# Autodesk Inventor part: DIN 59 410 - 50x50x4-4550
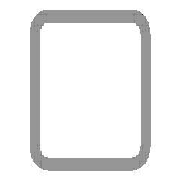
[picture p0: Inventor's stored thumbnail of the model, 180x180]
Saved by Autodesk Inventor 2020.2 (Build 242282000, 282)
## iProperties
Manager: www.cadconsulting.pl
Company: Fabian Stasiak CAD Consulting
IsCustomPart: 1
_CCFamilyMember: 40
_CCFamilyDisplayName: DIN 59410 (Kwadrat) - Rurki stalowe o przekroju kwadratowym formowane na gorąco
_FrameMemberDoc: Frame Member File
_Version: 15.0.0
_GetPNFromCC: 1
Created: 2015-01
Part Number: DIN 59 410 - 50x50x4-4550
Material: Stal, miękka
Description: Rurki stalowe o przekroju kwadratowym formowane na gorąco
Document SubType Name: Modellieren
Standard: DIN
Designer: F.Stasiak
Standards Organization: DIN
Language: pl-PL
Size Designation: 50x50x4
Categories: <MemberInstance><Categories><Category DisplayName="Kształtowniki konstrukcyjne" InternalName="089c4875-fa83-4c05-b084-43b9cc11f5ed" Mnemonic="GRDR"><CategoryPar
Stock Number: 50x50x4
Density: 7.85 g/cm^3
Appearance: Częściowo polerowana
Mass: 24543.7 g
Surface Area: 15652.6 cm^2
Volume: 3126.58 cm^3
Catalog Web Link: www.expertbooks.pl
G_L: 4550,000 mm
G_W: 50,000 mm
G_H: 50,000 mm
+2A0B5DE6-791F-402A-8B32-3269641191C7+CUTDETAIL1: Połączenie narożnikowe 45,00 deg
+B6354725-C38D-4B68-BB5C-FC2418608E11+CUTDETAIL2: Połączenie narożnikowe 45,00 deg
Author: F.Stasiak
Subject: Zbiór ćwiczeń. Autodesk Inventor 2020. Kurs Professional
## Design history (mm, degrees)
node "Płaszczyzna początkowa"
node "Płaszczyzna końcowa"
sketch "Szkic1"
  geometry: L1 (-17, 25)-(17, 25); L2 (25, 17)-(25, -17); L3 (17, -25)-(-17, -25); L4 (-25, -17)-(-25, 17); L5 (-36.682, 0)-(36.682, 0) reference; L6 (0, -36.682)-(0, 36.682) reference; L7 (-17, 21)-(17, 21); L8 (21, 17)-(21, -17); L9 (17, -21)-(-17, -21); L10 (-21, -17)-(-21, 17); A1 r 8 centre (-17, 17) between (-17, 25) and (-25, 17); A2 r 8 centre (17, 17) between (25, 17) and (17, 25); A3 r 8 centre (17, -17) between (17, -25) and (25, -17); A4 r 8 centre (-17, -17) between (-25, -17) and (-17, -25); A5 r 4 centre (-17, 17) between (-17, 21) and (-21, 17); A6 r 4 centre (17, 17) between (21, 17) and (17, 21); A7 r 4 centre (17, -17) between (17, -21) and (21, -17); A8 r 4 centre (-17, -17) between (-21, -17) and (-17, -21); 3 further points
  constraints: 16 end point, 16 point on circle, 8 centre point, 8 tangent, 6 point on line, 4 parallel, 3 equal radius, 3 perpendicular, 1 horizontal, 7 other
  dimensions: "b" = 50 distance of point (-25, 25) point (25, 25); "msp_r" = 8 radius of A1 (= 2 x ParT); "d8" = 25 distance between parallel lines of L4 L6 (= d9); "d9" = 25 distance between parallel lines of L3 L5 (= 0.5 x b); "d10" = 4 distance between parallel lines of L3 L9 (= ParT)
extrude "Bryła" new body sketch "Szkic1" taper "d4" = 0 deg; stored distance "NLG" = 10
node "Driven Length"
  sketch "Sketch2"
    geometry: L1 (0, 0)-(10, 0) reference
    constraints: 2 end point, 1 horizontal
  workplane "Work Plane3"
  sketch "Sketch3"
    geometry: L1 (-2, -25)-(12, -25) reference; L2 (-2, 4525)-(12, 4525) reference
    dimensions: "d14" = 4550 distance between parallel lines of L1 L2 (derived)
node "Płaszczyzna konstrukcyjna4"
feature "Podział1"
node "Płaszczyzna konstrukcyjna5"
feature "Podział2"
body "Solid1"
other parameters: "ParT" = 4, "G_OFFSET_START" = 25 [user parameter; used in 1 equation term], "G_OFFSET_END" = 25 [user parameter; used in 1 equation term], "d11" = -25 (= -G_OFFSET_START), "d12" = 4525 (= G_OFFSET_END + B_L), "G_L" = 4550 (= d14) [user parameter], "d13" = 90 deg
